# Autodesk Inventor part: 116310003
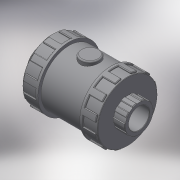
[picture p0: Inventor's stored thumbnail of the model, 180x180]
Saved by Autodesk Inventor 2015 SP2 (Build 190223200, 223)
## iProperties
Created: 2017-11
Part Number: 116310003
Material: Generic
Description: PLASSON AIR RELEASE VALVE THR PVC 3/8"
Document SubType Name: Modeling
Designer: KIM
Density: 1 g/cm^3
Appearance: Default
Author: KIM
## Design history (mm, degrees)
derived "116310 - 116910.ipt"
feature "Solid1::116310 - 116910.ipt"
tag "TaggingFeature1"
body "Solid1"
other parameters: "d0" = 71, "d1" = 14.95, "d2" = 45, "d3" = 12, "d4" = 11.96, "d5" = 8.4, "d7" = 20.93, "d8" = 40.5, "d13" = 0.4485, "d23" = 12, "d24" = 43.2, "d25" = 0.299, "d26" = 0.4485, "d27" = 6.75, "d28" = 3.375, "d29" = 9, "d30" = 0, "d35" = 0.4485, "d39" = 22.5, "d45" = 360 deg, "d47" = 0.299, "d50" = 22.5, "d51" = 13.5, "d53" = 0, "d54" = 0.9, "d55" = 2.99, "d56" = 1.495, "d58" = 0, "d59" = 0.4485, "d61" = 360 deg, "G_" = 14.95, "l_" = 12, "H_" = 71, "K_" = 45
